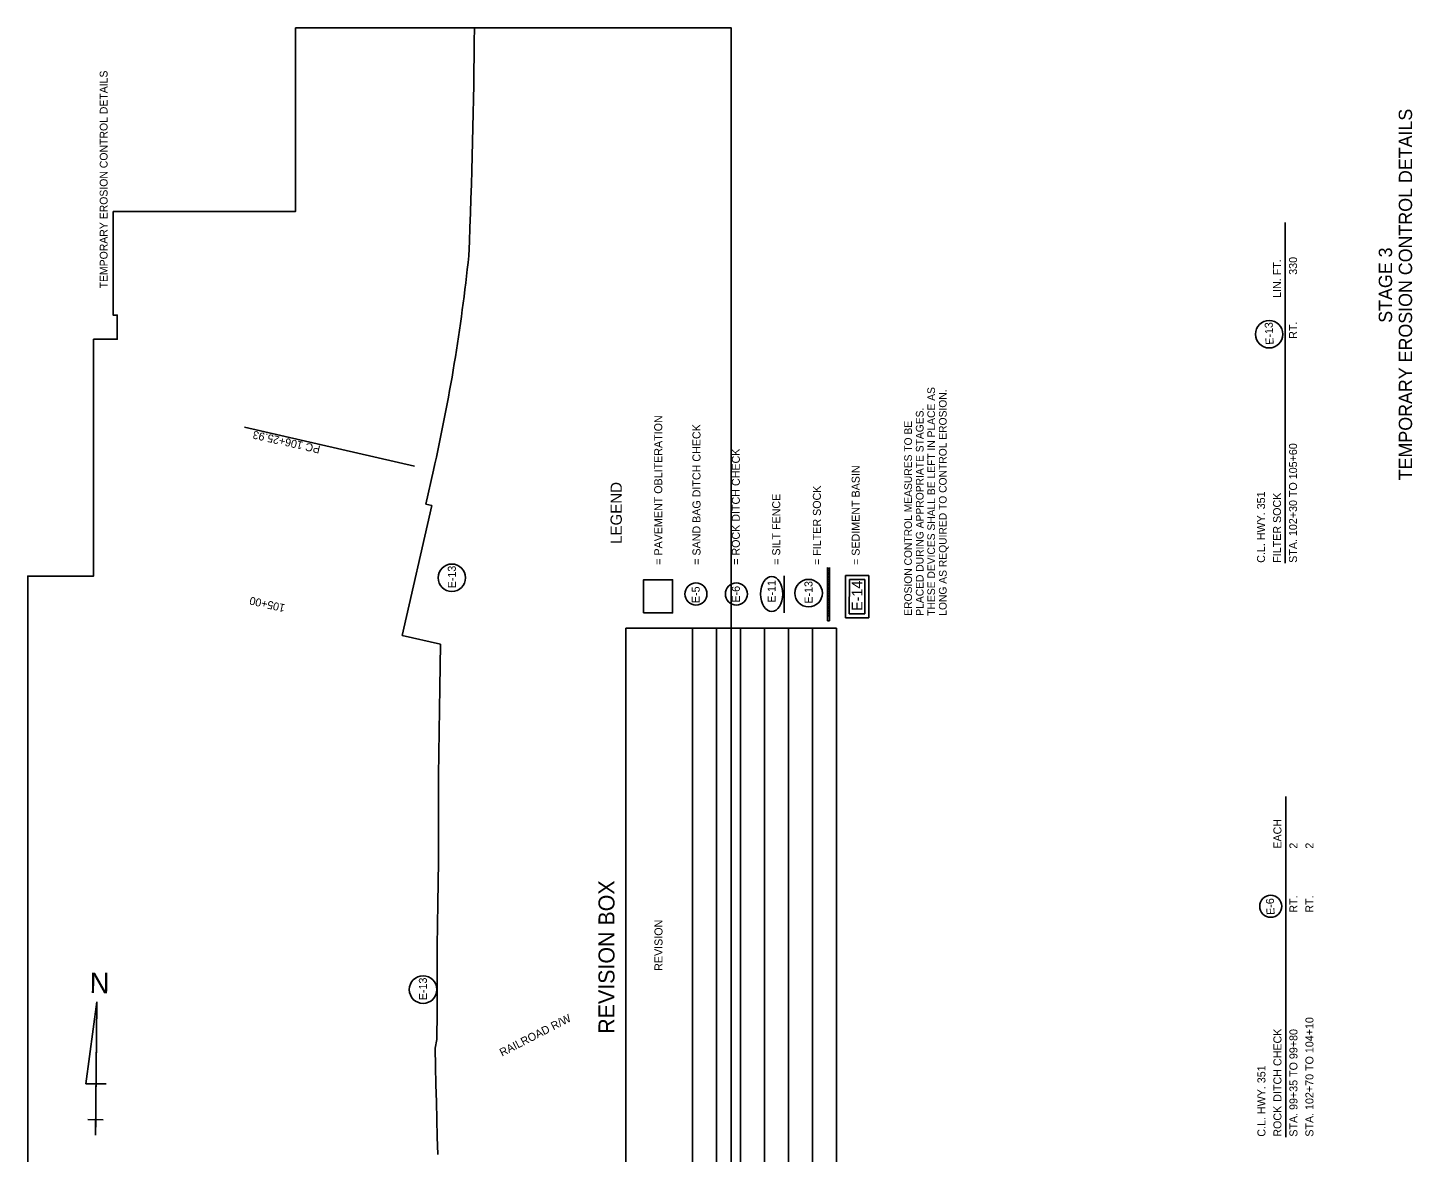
# Model space of a CAD drawing. Extents: x 1712161 to 1713203, y 549259 to 550855.
# Drawn here: x 1712161 to 1713199, y 550011 to 550855 of the extents above; entities that cross this region are included whole.
import ezdxf

# ---------------------------------------------------------------- set-up
doc = ezdxf.new("R2010")
doc.units = 0
for name, color, linetype in [('R_Erosion_STG 2', 7, 'Continuous'), ('R_Horz Alg', 7, 'Continuous'), ('R_Horz Alg Annot', 7, 'Continuous'), ('R_No Plot', 7, 'Continuous'), ('R_Proposed Const Limits_Fill', 7, 'Continuous')]:
    doc.layers.add(name, color=color, linetype=linetype)

msp = doc.modelspace()

# ---------------------------------------------------------------- linework, layer by layer
at = {"layer": 'R_Erosion_STG 2'}
for p, q in [((1712464.9, 550522.6), (1712459.2, 550497.3)), ((1712464.9, 550522.6), (1712459.2, 550497.3)), ((1712463.6, 550496.3), (1712441.5, 550398.8)), ((1712463.6, 550496.3), (1712441.5, 550398.8)), ((1712459.2, 550497.3), (1712463.6, 550496.3)), ((1712459.2, 550497.3), (1712463.6, 550496.3)), ((1712441.5, 550398.8), (1712470.1, 550392.3)), ((1712441.5, 550398.8), (1712470.1, 550392.3))]:
    msp.add_line(p, q, dxfattribs=at)
for points in [[(1712361.5, 550854.5), (1712688.2, 550854.5), (1712688.2, 549259.2), (1712160.6, 549259.2), (1712160.6, 550443.2), (1712210, 550443.2), (1712210, 550620.8), (1712227.8, 550620.8), (1712227.8, 550639), (1712224.6, 550639), (1712224.6, 550716.7)], [(1712224.6, 550716.7), (1712361.5, 550716.7), (1712361.5, 550854.5)], [(1712688.2, 549999.7), (1712688.2, 550854.5), (1712495.7, 550854.5)], [(1712688.2, 549999.7), (1712688.2, 550854.5), (1712495.7, 550854.5)], [(1712470.1, 550392.3), (1712470.1, 550392.2), (1712469.9, 550376), (1712469.7, 550359.8), (1712469.5, 550343.3), (1712469.2, 550326.8), (1712469, 550310.3), (1712468.7, 550293.8), (1712468.7, 550277.7), (1712468.7, 550261.6), (1712468.6, 550245.4), (1712468.6, 550229.3), (1712468.4, 550213.4), (1712468.1, 550197.6), (1712467.9, 550181.7), (1712467.6, 550165.8), (1712467.7, 550141.1), (1712467.8, 550116.5), (1712467.5, 550095.6), (1712466.2, 550089.2), (1712466.5, 550075.5), (1712466.7, 550061.9), (1712467.1, 550048.8), (1712467.4, 550035.7), (1712467.8, 550022.6), (1712468.1, 550009.5)], [(1712470.1, 550392.3), (1712470.1, 550392.2), (1712469.9, 550376), (1712469.7, 550359.8), (1712469.5, 550343.3), (1712469.2, 550326.8), (1712469, 550310.3), (1712468.7, 550293.8), (1712468.7, 550277.7), (1712468.7, 550261.6), (1712468.6, 550245.4), (1712468.6, 550229.3), (1712468.4, 550213.4), (1712468.1, 550197.6), (1712467.9, 550181.7), (1712467.6, 550165.8), (1712467.7, 550141.1), (1712467.8, 550116.5), (1712467.5, 550095.6), (1712466.2, 550089.2), (1712466.5, 550075.5), (1712466.7, 550061.9), (1712467.1, 550048.8), (1712467.4, 550035.7), (1712467.8, 550022.6), (1712468.1, 550009.5)]]:
    msp.add_lwpolyline(points, dxfattribs=at)
for centre in [(1712478.7, 550442), (1712457.1, 550133.1)]:
    msp.add_circle(centre, 10.3, dxfattribs=at)
for centre, radius, start, end in [((1706966.7, 550904.5), 5529.2, 357.7082, 359.4818), ((1706966.7, 550904.5), 5529.2, 357.7082, 359.4818), ((1711136.1, 550824.3), 1362.6, 347.2066, 354.0638), ((1711136.1, 550824.3), 1362.6, 347.2066, 354.0638)]:
    msp.add_arc(centre, radius, start, end, dxfattribs=at)
at = {"layer": 'R_Horz Alg'}
for p, q in [((1712212.5, 550124), (1712204.2, 550062.5)), ((1712211.4, 550024), (1712212.5, 550124)), ((1712212.5, 550124), (1712211.7, 550047.1)), ((1712204.2, 550062.5), (1712219.5, 550062.4)), ((1712211.4, 550024), (1712211.7, 550047.1)), ((1712211.6, 550035.5), (1712205.8, 550035.6)), ((1712205.8, 550035.6), (1712217.3, 550035.5)), ((1712211.4, 550024), (1712211.6, 550035.5))]:
    msp.add_line(p, q, dxfattribs=at)
at = {"layer": 'R_Horz Alg Annot'}
for p, q in [((1712688.2, 550628.7), (1712688.2, 550854.5)), ((1713103.8, 550452.9), (1713103.8, 550708.4)), ((1712688.2, 550404.2), (1712688.2, 550411.8)), ((1712609.2, 549917.3), (1712609.2, 550404.2)), ((1712609.2, 550404.2), (1712767.2, 550404.2)), ((1712659.2, 549917.3), (1712659.2, 550404.2)), ((1712677.2, 549917.3), (1712677.2, 550404.2)), ((1712695.2, 549917.3), (1712695.2, 550404.2)), ((1712713.2, 549917.3), (1712713.2, 550404.2)), ((1712731.2, 549917.3), (1712731.2, 550404.2)), ((1712749.2, 549917.3), (1712749.2, 550404.2)), ((1712767.2, 549917.3), (1712767.2, 550404.2)), ((1713104.1, 550022.5), (1713104.1, 550278))]:
    msp.add_line(p, q, dxfattribs=at)
msp.add_lwpolyline([(1712450.8, 550525.8), (1712323.3, 550554.9)], dxfattribs=at)
at = {"layer": 'R_No Plot'}
msp.add_lwpolyline([(1712622.5, 550415.6), (1712622.5, 550440.5), (1712644.3, 550440.5), (1712644.3, 550415.6)], close=True, dxfattribs=at)
at = {"layer": 'R_Proposed Const Limits_Fill'}
for p, q in [((1712760.5, 550409.6), (1712760.5, 550449.6)), ((1712762, 550448.1), (1712760.5, 550449.6)), ((1712762, 550446.7), (1712760.5, 550448.2)), ((1712762, 550445.3), (1712760.5, 550446.8)), ((1712762, 550449.5), (1712761.9, 550449.6)), ((1712762, 550449.6), (1712762, 550409.6)), ((1712762, 550443.9), (1712760.5, 550445.4)), ((1712762, 550442.5), (1712760.5, 550444)), ((1712762, 550441.1), (1712760.5, 550442.6)), ((1712762, 550439.6), (1712760.5, 550441.1)), ((1712762, 550438.2), (1712760.5, 550439.7)), ((1712762, 550436.8), (1712760.5, 550438.3)), ((1712762, 550435.4), (1712760.5, 550436.9)), ((1712773.9, 550443.6), (1712791.4, 550443.6)), ((1712773.9, 550412), (1712773.9, 550443.6)), ((1712776.8, 550415), (1712776.9, 550440.7)), ((1712776.9, 550440.7), (1712788.5, 550440.7)), ((1712788.5, 550415), (1712788.5, 550440.7)), ((1712791.4, 550412), (1712791.4, 550443.6)), ((1712762, 550434), (1712760.5, 550435.5)), ((1712762, 550432.6), (1712760.5, 550434.1)), ((1712762, 550431.2), (1712760.5, 550432.7)), ((1712762, 550429.7), (1712760.5, 550431.2)), ((1712762, 550428.3), (1712760.5, 550429.8)), ((1712762, 550426.9), (1712760.5, 550428.4)), ((1712762, 550425.5), (1712760.5, 550427)), ((1712762, 550424.1), (1712760.5, 550425.6)), ((1712762, 550422.7), (1712760.5, 550424.2)), ((1712762, 550421.3), (1712760.5, 550422.8)), ((1712762, 550419.8), (1712760.5, 550421.3)), ((1712762, 550418.4), (1712760.5, 550419.9)), ((1712762, 550417), (1712760.5, 550418.5)), ((1712762, 550415.6), (1712760.5, 550417.1)), ((1712762, 550414.2), (1712760.5, 550415.7)), ((1712776.8, 550415), (1712788.5, 550415)), ((1712762, 550412.8), (1712760.5, 550414.3)), ((1712762, 550409.6), (1712760.5, 550409.6)), ((1712773.9, 550412), (1712791.4, 550412))]:
    msp.add_line(p, q, dxfattribs=at)
msp.add_lwpolyline([(1712728, 550415.7), (1712728, 550443.5)], dxfattribs=at)
for centre, radius in [((1713091.7, 550624.6), 10.3), ((1712661.8, 550429.8), 8.26), ((1712692.1, 550429.8), 8.26), ((1712746.3, 550430.5), 10.3), ((1713092.9, 550195.6), 8.26)]:
    msp.add_circle(centre, radius, dxfattribs=at)
msp.add_ellipse((1712718.6, 550429.8), major_axis=(0, 13.1), ratio=0.638788, dxfattribs=at)

# ---------------------------------------------------------------- texts
at = {"layer": 'R_Erosion_STG 2'}
for p in [(1712481.8, 550434.1), (1712460.1, 550125.2)]:
    msp.add_text('E-13', height=6, rotation=90.4005, dxfattribs=at).set_placement(p)
at = {"layer": 'R_Horz Alg'}
for s, height, rotation, p in [('TEMPORARY EROSION CONTROL DETAILS', 5.862, 90, (1712220.5, 550659)), ('N', 15.4, 359.3683, (1712207, 550130.5))]:
    msp.add_text(s, height=height, rotation=rotation, dxfattribs=at).set_placement(p)
at = {"layer": 'R_Horz Alg Annot'}
for s, height, rotation, p in [('TEMPORARY EROSION CONTROL DETAILS', 10, 90, (1713198.9, 550515.1)), ('STAGE 3', 10, 90, (1713183.9, 550633.2)), ('   LIN. FT. ', 6, 90, (1713100.6, 550645.2)), ('330', 6, 90, (1713112.6, 550669.2)), ('RT.', 6, 90, (1713112.6, 550621.2)), ('PC 106+25.93', 6, 167.2066, (1712380.5, 550540.9)), ('STA. 102+30 TO 105+60', 6, 90, (1713112.6, 550453.2)), ('C.L. HWY. 351', 6, 90, (1713088.6, 550453.2)), ('FILTER SOCK', 6, 90, (1713100.6, 550453.2)), ('105+00', 6, 167.2066, (1712354.1, 550421.9)), ('EACH', 6, 90, (1713100.9, 550238.8)), ('2', 6, 90, (1713112.9, 550238.8)), ('2', 6, 90, (1713124.9, 550238.8)), ('REVISION BOX', 12, 90, (1712600.7, 550100)), ('RT. ', 6, 90, (1713112.9, 550190.8)), ('RT.', 6, 90, (1713124.9, 550190.8)), ('REVISION', 6, 90, (1712636.7, 550147.2)), ('RAILROAD R/W', 6, 27.2066, (1712516.4, 550082.8)), (' DITCH CHECK', 6, 90, (1713100.9, 550046.8)), ('STA. 102+70 TO 104+10', 6, 90, (1713124.9, 550022.8)), ('STA. 99+35 TO 99+80', 6, 90, (1713112.9, 550022.8)), ('C.L. HWY. 351', 6, 90, (1713088.9, 550022.8)), ('ROCK', 6, 90, (1713100.9, 550022.8))]:
    msp.add_text(s, height=height, rotation=rotation, dxfattribs=at).set_placement(p)
at = {"layer": 'R_Proposed Const Limits_Fill'}
for s, height, rotation, p in [('E-13', 6, 92.7601, (1713095.1, 550616.9)), ('THESE DEVICES SHALL BE LEFT IN PLACE AS ', 5.769, 90, (1712841.1, 550413.5)), ('LONG AS REQUIRED TO CONTROL EROSION.', 5.769, 90, (1712849.8, 550413.5)), ('= PAVEMENT OBLITERATION', 6, 90, (1712636.5, 550451.7)), ('PLACED DURING APPROPRIATE STAGES. ', 5.769, 90, (1712832.5, 550413.5)), ('= SAND BAG DITCH CHECK', 6, 90, (1712665.2, 550451.7)), ('EROSION CONTROL MEASURES TO BE', 5.769, 90, (1712823.8, 550413.5)), ('= ROCK DITCH CHECK', 6, 90, (1712694.7, 550451.7)), ('= SEDIMENT BASIN', 6, 90, (1712784.6, 550451.6)), ('LEGEND', 8.44, 90, (1712606.2, 550467.4)), ('= FILTER SOCK', 6, 90, (1712755.5, 550451.6)), ('= SILT FENCE', 6, 90, (1712725, 550451.7)), ('E-11', 6, 90.2144, (1712721.6, 550423.3)), ('E-13', 6, 90.4005, (1712749.3, 550422.6)), ('E-14', 8, 89.9884, (1712786.7, 550417.2)), ('E-5 ', 6, 90, (1712664.6, 550423)), ('E-6 ', 6, 90.4005, (1712694.8, 550423.4)), ('E-6 ', 6, 92.7601, (1713095.8, 550189.3))]:
    msp.add_text(s, height=height, rotation=rotation, dxfattribs=at).set_placement(p)

doc.saveas('drawing.dxf')
